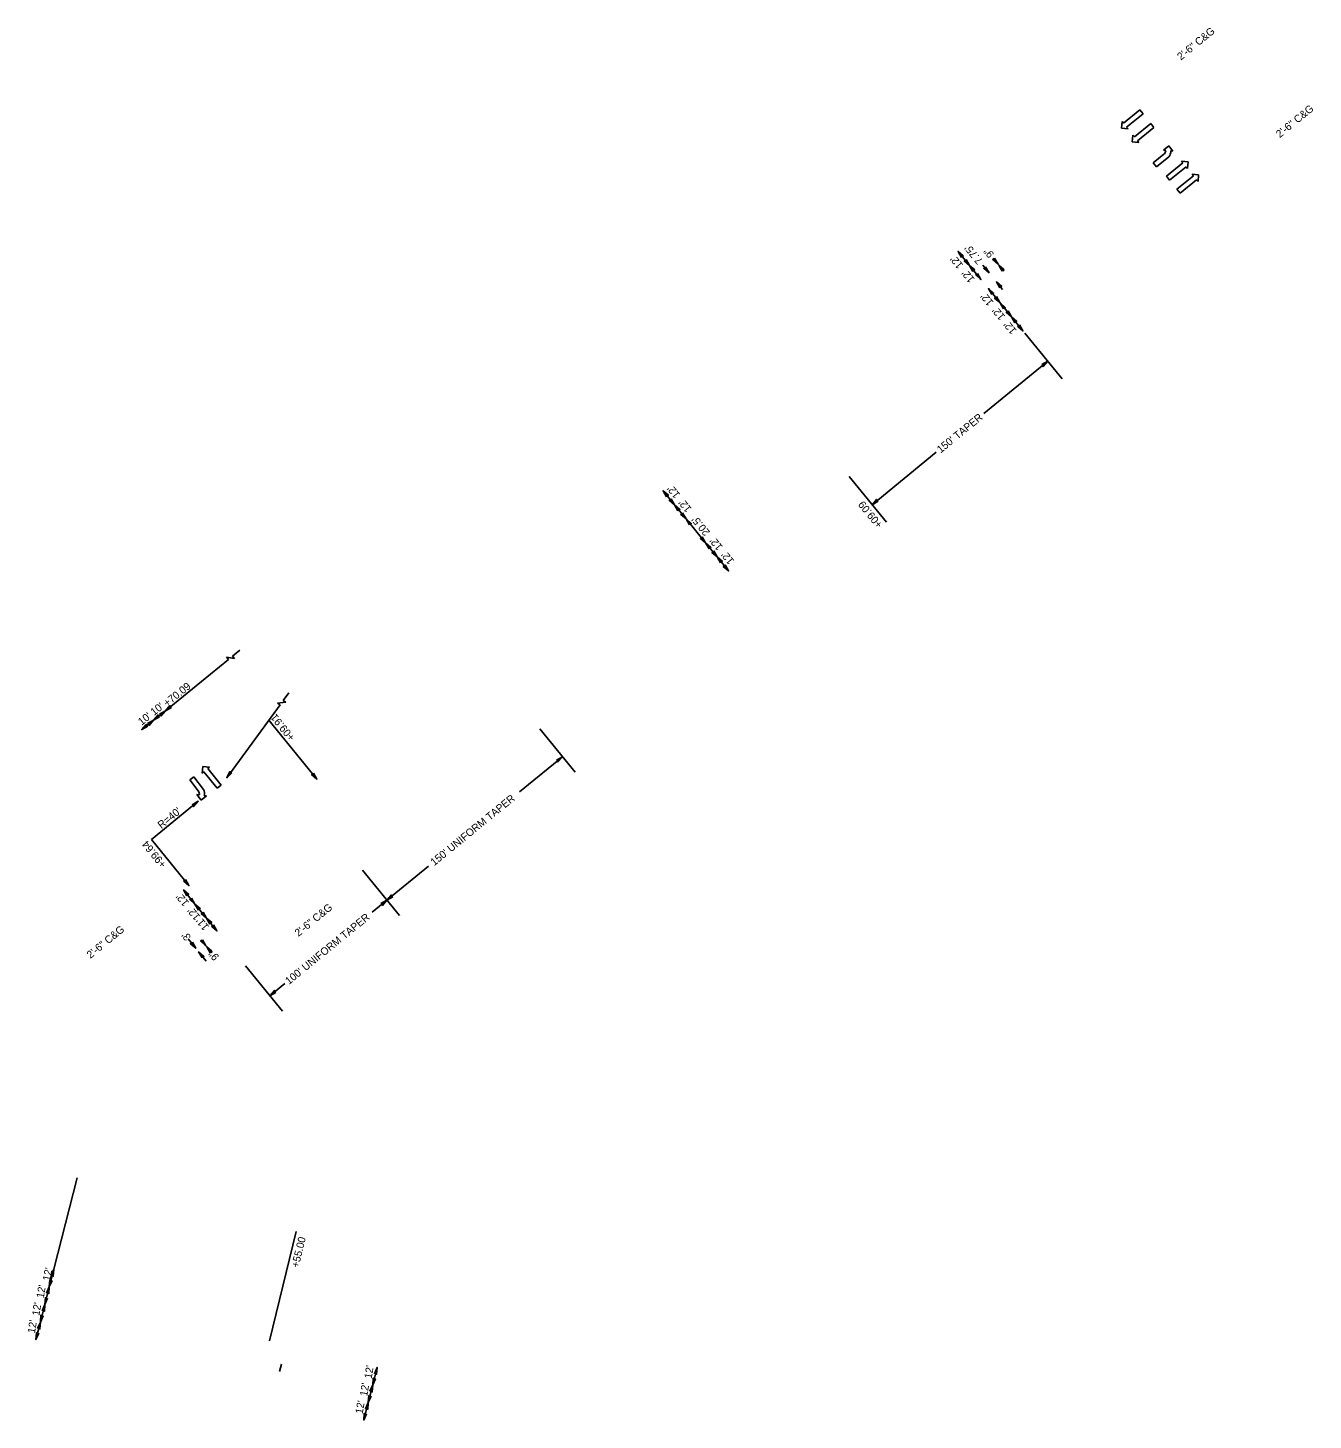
# Model space of a CAD drawing. Extents: x 2320991 to 2332664, y 598057 to 612602.
# Drawn here: x 2322011 to 2322862, y 598057 to 598978 of the extents above; entities that cross this region are included whole.
import ezdxf

# ---------------------------------------------------------------- set-up
doc = ezdxf.new("R2010")
doc.units = 0
for name, color, linetype in [('Prop Dimension', 7, 'Continuous'), ('Prop Dimension Text', 7, 'Continuous'), ('Prop Horizontal Alignment Tick Small', 7, 'Continuous'), ('Prop Lane Arrow CELL', 7, 'Continuous'), ('Prop Terminator CELL', 7, 'Continuous')]:
    doc.layers.add(name, color=color, linetype=linetype)

msp = doc.modelspace()

# ---------------------------------------------------------------- linework, layer by layer
at = {"layer": 'Prop Dimension'}
for p, q in [((2322626.9, 598830.22), (2322634.48, 598820.92)), ((2322634.48, 598820.92), (2322642.07, 598811.62)), ((2322643.28, 598821.1), (2322647.39, 598816.06)), ((2322650.03, 598825.85), (2322653.34, 598821.79)), ((2322653.81, 598821.21), (2322657.12, 598817.15)), ((2322646.98, 598805.62), (2322654.56, 598796.32)), ((2322652.29, 598810.06), (2322656.4, 598805.02)), ((2322654.66, 598796.21), (2322662.25, 598786.92)), ((2322662.25, 598786.92), (2322669.84, 598777.62)), ((2322671.01, 598776.19), (2322695.7, 598745.94)), ((2322643.86, 598722.98), (2322686.22, 598757.56)), ((2322570, 598662.68), (2322612.49, 598697.37)), ((2322554.79, 598681.31), (2322579.48, 598651.06)), ((2322431.75, 598671.87), (2322439.34, 598662.57)), ((2322439.34, 598662.57), (2322446.93, 598653.28)), ((2322446.93, 598653.28), (2322459.89, 598637.4)), ((2322459.89, 598637.4), (2322467.48, 598628.1)), ((2322467.48, 598628.1), (2322475.07, 598618.81)), ((2322146.88, 598562.55), (2322151.73, 598566.51)), ((2322102.46, 598526.28), (2322144.08, 598560.27)), ((2322180.43, 598533.17), (2322184.17, 598538.19)), ((2322086.75, 598513.9), (2322102.46, 598526.28)), ((2322143.07, 598482.05), (2322178.27, 598530.27)), ((2322202.68, 598481.18), (2322170.87, 598520.14)), ((2322350.22, 598514.3), (2322373.49, 598485.79)), ((2322336.65, 598472.66), (2322365.19, 598495.96)), ((2322124.13, 598466.48), (2322093.15, 598441.19)), ((2322118.02, 598410.74), (2322093.15, 598441.19)), ((2322232.84, 598420.89), (2322257.29, 598390.93)), ((2322248.99, 598401.09), (2322276.56, 598423.6)), ((2322122.01, 598398.51), (2322114.42, 598407.8)), ((2322129.6, 598389.21), (2322122.01, 598398.51)), ((2322248.99, 598401.09), (2322239.34, 598393.21)), ((2322136.56, 598380.69), (2322129.6, 598389.21)), ((2322117.44, 598375.41), (2322122.5, 598369.22)), ((2322125.95, 598374.92), (2322129.26, 598370.86)), ((2322129.74, 598370.28), (2322133.05, 598366.22)), ((2322124.4, 598366.89), (2322128.59, 598361.76)), ((2322124.4, 598366.89), (2322129.46, 598360.7)), ((2322155.37, 598357.65), (2322179.83, 598327.69)), ((2322181.49, 598345.99), (2322171.53, 598337.85)), ((2322028.68, 598157), (2322043.95, 598217.49)), ((2322171.25, 598109.47), (2322189, 598181.97)), ((2322028.55, 598156.9), (2322025.61, 598145.27)), ((2322025.61, 598145.27), (2322022.67, 598133.63)), ((2322022.67, 598133.63), (2322019.72, 598122)), ((2322019.72, 598122), (2322016.78, 598110.37)), ((2322242.53, 598092.01), (2322239.59, 598080.37)), ((2322239.59, 598080.37), (2322236.65, 598068.74)), ((2322236.65, 598068.74), (2322233.7, 598057.11))]:
    msp.add_line(p, q, dxfattribs=at)
at = {"layer": 'Prop Dimension Text'}
for p, q in [((2322146.88, 598562.55), (2322148.15, 598561)), ((2322142.82, 598561.82), (2322148.15, 598561)), ((2322144.08, 598560.27), (2322142.82, 598561.82)), ((2322176.67, 598531.47), (2322182.03, 598531.97)), ((2322178.27, 598530.27), (2322176.67, 598531.47)), ((2322180.43, 598533.17), (2322182.03, 598531.97))]:
    msp.add_line(p, q, dxfattribs=at)
at = {"layer": 'Prop Horizontal Alignment Tick Small'}
msp.add_line((2322177.99, 598089.28), (2322179.21, 598094.13), dxfattribs=at)
at = {"layer": 'Prop Lane Arrow CELL'}
for p, q in [((2322736.34, 598914.96), (2322747.21, 598923.78)), ((2322747.21, 598923.78), (2322749.29, 598921.22)), ((2322734.97, 598911.66), (2322735.4, 598916.13)), ((2322735.4, 598916.13), (2322736.34, 598914.96)), ((2322749.29, 598921.22), (2322738.42, 598912.4)), ((2322743.55, 598905.91), (2322754.42, 598914.73)), ((2322754.42, 598914.73), (2322756.5, 598912.17)), ((2322739.37, 598911.23), (2322734.97, 598911.66)), ((2322738.42, 598912.4), (2322739.37, 598911.23)), ((2322742.17, 598902.61), (2322742.6, 598907.08)), ((2322742.6, 598907.08), (2322743.55, 598905.91)), ((2322756.5, 598912.17), (2322745.63, 598903.35)), ((2322745.63, 598903.35), (2322746.57, 598902.19)), ((2322746.57, 598902.19), (2322742.17, 598902.61)), ((2322763.12, 598894.52), (2322756.03, 598888.73)), ((2322766.37, 598899.95), (2322762.85, 598897.14)), ((2322762.85, 598897.14), (2322764.33, 598896.99)), ((2322769.12, 598896.51), (2322766.37, 598899.95)), ((2322767.64, 598896.65), (2322769.12, 598896.51)), ((2322756.03, 598888.73), (2322758.12, 598886.17)), ((2322758.12, 598886.17), (2322766.29, 598892.85)), ((2322764.78, 598879.89), (2322775.65, 598888.72)), ((2322777.73, 598886.15), (2322766.86, 598877.33)), ((2322775.65, 598888.72), (2322774.7, 598889.88)), ((2322774.7, 598889.88), (2322779.1, 598889.46)), ((2322778.67, 598884.99), (2322777.73, 598886.15)), ((2322779.1, 598889.46), (2322778.67, 598884.99)), ((2322766.86, 598877.33), (2322764.78, 598879.89)), ((2322771.77, 598871.32), (2322782.65, 598880.15)), ((2322784.73, 598877.58), (2322773.85, 598868.76)), ((2322782.65, 598880.15), (2322781.7, 598881.31)), ((2322781.7, 598881.31), (2322786.1, 598880.89)), ((2322785.67, 598876.42), (2322784.73, 598877.58)), ((2322786.1, 598880.89), (2322785.67, 598876.42)), ((2322773.85, 598868.76), (2322771.77, 598871.32)), ((2322126.78, 598485.05), (2322127.2, 598489.45)), ((2322127.2, 598489.45), (2322131.67, 598489.02)), ((2322131.67, 598489.02), (2322130.5, 598488.07)), ((2322118.61, 598480.6), (2322121.22, 598482.61)), ((2322124.19, 598473.35), (2322118.61, 598480.6)), ((2322121.22, 598482.61), (2322127.66, 598474.26)), ((2322127.94, 598485.99), (2322126.78, 598485.05)), ((2322136.76, 598475.12), (2322127.94, 598485.99)), ((2322130.5, 598488.07), (2322139.32, 598477.2)), ((2322126.12, 598467.32), (2322123.33, 598470.86)), ((2322123.33, 598470.86), (2322124.8, 598470.67)), ((2322139.32, 598477.2), (2322136.76, 598475.12)), ((2322129.57, 598470.05), (2322126.12, 598467.32)), ((2322128.1, 598470.24), (2322129.57, 598470.05))]:
    msp.add_line(p, q, dxfattribs=at)
for centre, radius, start, end in [((2322761.07, 598897.05), 3.27, 309.22799, 358.88617), ((2322762.41, 598896.35), 5.25, 317.90406, 3.21576), ((2322121.61, 598471.35), 3.27, 347.95273, 37.61091), ((2322123.07, 598471.72), 5.25, 343.62314, 28.93483)]:
    msp.add_arc(centre, radius, start, end, dxfattribs=at)
at = {"layer": 'Prop Terminator CELL'}
for points in [[(2322629.14, 598826.24), (2322626.9, 598830.22), (2322630.38, 598827.22), (2322629.39, 598827.16)], [(2322632.24, 598824.9), (2322634.48, 598820.92), (2322631, 598823.92), (2322631.99, 598823.98)], [(2322636.73, 598816.94), (2322634.48, 598820.92), (2322637.97, 598817.92), (2322636.98, 598817.86)], [(2322651.09, 598825.77), (2322653.34, 598821.79), (2322649.86, 598824.79), (2322650.84, 598824.85)], [(2322656.06, 598817.23), (2322653.81, 598821.21), (2322657.29, 598818.21), (2322656.31, 598818.15)], [(2322639.83, 598815.6), (2322642.07, 598811.62), (2322638.59, 598814.62), (2322639.58, 598814.68)], [(2322645.14, 598820.04), (2322647.39, 598816.06), (2322643.91, 598819.06), (2322644.89, 598819.12)], [(2322649.22, 598801.65), (2322646.97, 598805.62), (2322650.46, 598802.62), (2322649.47, 598802.56)], [(2322654.54, 598806.08), (2322652.29, 598810.06), (2322655.77, 598807.06), (2322654.79, 598807)], [(2322652.32, 598800.3), (2322654.56, 598796.32), (2322651.08, 598799.32), (2322652.07, 598799.38)], [(2322656.9, 598792.24), (2322654.66, 598796.21), (2322658.14, 598793.21), (2322657.16, 598793.15)], [(2322660, 598790.89), (2322662.25, 598786.92), (2322658.77, 598789.92), (2322659.75, 598789.98)], [(2322664.49, 598782.94), (2322662.25, 598786.92), (2322665.73, 598783.92), (2322664.75, 598783.86)], [(2322667.59, 598781.6), (2322669.84, 598777.62), (2322666.36, 598780.62), (2322667.34, 598780.68)], [(2322682.24, 598755.31), (2322686.22, 598757.56), (2322683.22, 598754.07), (2322683.16, 598755.06)], [(2322434, 598667.89), (2322431.75, 598671.87), (2322435.23, 598668.87), (2322434.25, 598668.81)], [(2322437.09, 598666.55), (2322439.34, 598662.57), (2322435.86, 598665.57), (2322436.84, 598665.63)], [(2322573.97, 598664.92), (2322570, 598662.68), (2322573, 598666.16), (2322573.06, 598665.17)], [(2322441.58, 598658.6), (2322439.34, 598662.57), (2322442.82, 598659.57), (2322441.84, 598659.51)], [(2322444.68, 598657.25), (2322446.93, 598653.28), (2322443.45, 598656.28), (2322444.43, 598656.34)], [(2322449.17, 598649.3), (2322446.93, 598653.28), (2322450.41, 598650.28), (2322449.43, 598650.22)], [(2322457.65, 598641.37), (2322459.89, 598637.4), (2322456.41, 598640.4), (2322457.39, 598640.46)], [(2322462.14, 598633.42), (2322459.89, 598637.4), (2322463.37, 598634.4), (2322462.39, 598634.34)], [(2322465.24, 598632.08), (2322467.48, 598628.1), (2322464, 598631.1), (2322464.98, 598631.16)], [(2322469.73, 598624.13), (2322467.48, 598628.1), (2322470.96, 598625.1), (2322469.98, 598625.04)], [(2322472.82, 598622.78), (2322475.07, 598618.81), (2322471.59, 598621.81), (2322472.57, 598621.87)], [(2322098.48, 598524.04), (2322102.46, 598526.28), (2322099.46, 598522.8), (2322099.4, 598523.79)], [(2322106.44, 598528.53), (2322102.46, 598526.28), (2322105.46, 598529.77), (2322105.52, 598528.78)], [(2322090.73, 598516.15), (2322086.75, 598513.9), (2322089.75, 598517.38), (2322089.81, 598516.4)], [(2322090.63, 598517.85), (2322094.61, 598520.09), (2322091.61, 598516.61), (2322091.55, 598517.6)], [(2322098.58, 598522.34), (2322094.61, 598520.09), (2322097.61, 598523.58), (2322097.67, 598522.59)], [(2322361.21, 598493.71), (2322365.19, 598495.96), (2322362.19, 598492.47), (2322362.13, 598493.46)], [(2322146.35, 598485.23), (2322143.07, 598482.05), (2322145.09, 598486.18), (2322145.4, 598485.24)], [(2322200.43, 598485.16), (2322202.68, 598481.18), (2322199.2, 598484.18), (2322200.18, 598484.24)], [(2322120.16, 598464.24), (2322124.13, 598466.48), (2322121.13, 598463), (2322121.07, 598463.99)], [(2322116.67, 598403.83), (2322114.42, 598407.8), (2322117.91, 598404.8), (2322116.92, 598404.74)], [(2322115.77, 598414.71), (2322118.02, 598410.74), (2322114.54, 598413.74), (2322115.52, 598413.8)], [(2322119.77, 598402.48), (2322122.01, 598398.51), (2322118.53, 598401.51), (2322119.52, 598401.57)], [(2322124.26, 598394.53), (2322122.01, 598398.51), (2322125.49, 598395.51), (2322124.51, 598395.45)], [(2322245.02, 598398.85), (2322248.99, 598401.09), (2322245.99, 598397.61), (2322245.93, 598398.6)], [(2322252.97, 598403.34), (2322248.99, 598401.09), (2322251.99, 598404.58), (2322252.05, 598403.59)], [(2322127.36, 598393.19), (2322129.6, 598389.21), (2322126.12, 598392.21), (2322127.1, 598392.27)], [(2322131.85, 598385.24), (2322129.6, 598389.21), (2322133.08, 598386.21), (2322132.1, 598386.15)], [(2322134.31, 598384.67), (2322136.56, 598380.69), (2322133.08, 598383.69), (2322134.06, 598383.75)], [(2322120.26, 598373.19), (2322122.5, 598369.22), (2322119.02, 598372.22), (2322120, 598372.28)], [(2322127.02, 598374.84), (2322129.26, 598370.86), (2322125.78, 598373.86), (2322126.76, 598373.92)], [(2322131.98, 598366.3), (2322129.74, 598370.28), (2322133.22, 598367.28), (2322132.23, 598367.22)], [(2322126.65, 598362.92), (2322124.4, 598366.89), (2322127.88, 598363.89), (2322126.9, 598363.83)], [(2322175.51, 598340.1), (2322171.53, 598337.85), (2322174.53, 598341.34), (2322174.59, 598340.35)], [(2322027.47, 598149.44), (2322025.61, 598145.27), (2322025.94, 598149.85), (2322026.58, 598149.1)], [(2322026.7, 598152.73), (2322028.55, 598156.9), (2322028.22, 598152.32), (2322027.59, 598153.07)], [(2322023.75, 598141.09), (2322025.61, 598145.27), (2322025.28, 598140.68), (2322024.64, 598141.44)], [(2322020.81, 598129.46), (2322022.67, 598133.63), (2322022.33, 598129.05), (2322021.7, 598129.8)], [(2322024.52, 598137.81), (2322022.67, 598133.63), (2322023, 598138.22), (2322023.64, 598137.46)], [(2322017.87, 598117.83), (2322019.72, 598122), (2322019.39, 598117.42), (2322018.75, 598118.17)], [(2322021.58, 598126.17), (2322019.72, 598122), (2322020.06, 598126.58), (2322020.69, 598125.83)], [(2322018.63, 598114.54), (2322016.78, 598110.37), (2322017.11, 598114.95), (2322017.75, 598114.2)], [(2322241.45, 598084.54), (2322239.59, 598080.37), (2322239.92, 598084.95), (2322240.56, 598084.2)], [(2322240.68, 598087.83), (2322242.53, 598092.01), (2322242.2, 598087.42), (2322241.57, 598088.18)], [(2322237.73, 598076.2), (2322239.59, 598080.37), (2322239.26, 598075.79), (2322238.62, 598076.54)], [(2322234.79, 598064.57), (2322236.65, 598068.74), (2322236.31, 598064.16), (2322235.68, 598064.91)], [(2322238.5, 598072.91), (2322236.65, 598068.74), (2322236.98, 598073.32), (2322237.61, 598072.57)], [(2322235.56, 598061.28), (2322233.7, 598057.11), (2322234.04, 598061.69), (2322234.67, 598060.93)]]:
    msp.add_lwpolyline(points, close=True, dxfattribs=at)

# ---------------------------------------------------------------- texts
at = {"layer": 'Prop Dimension'}
msp.add_text('+55.00', height=5, rotation=76.23807, dxfattribs=at).set_placement((2322190.51, 598157.61))
at = {"layer": 'Prop Dimension Text'}
for s, rotation, p in [('2\'-6" C&G', 39.22799, (2322774.33, 598956.39)), ('2\'-6" C&G', 39.22799, (2322839.77, 598905.08)), ("7.75'", 129.22799, (2322643.64, 598824.19)), ('9"', 129.22799, (2322651.1, 598828.43)), ("12'", 129.22799, (2322630.61, 598821.22)), ("12'", 129.22799, (2322638.2, 598811.93)), ("12'", 129.22799, (2322650.69, 598796.63)), ("12'", 129.22799, (2322658.37, 598787.22)), ("12'", 129.22799, (2322665.96, 598777.92)), ("150' TAPER", 39.22799, (2322615.4, 598696.52)), ("12'", 129.22799, (2322443.35, 598669.38)), ("12'", 129.22799, (2322450.94, 598660.09)), ('+09.09', 129.22799, (2322577.31, 598649.68)), ("20.5'", 129.22799, (2322463.07, 598644.57)), ("12'", 129.22799, (2322471.5, 598634.91)), ("12'", 129.22799, (2322479.09, 598625.61)), ('+70.09', 38.71959, (2322103.6, 598528.8)), ("10'", 38.24817, (2322094.94, 598522.88)), ("10'", 38.24817, (2322086.72, 598516.4)), ('+09.91', 129.22799, (2322188.48, 598508.88)), ("150' UNIFORM TAPER", 39.22799, (2322280.31, 598423.52)), ("R=40'", 39.22799, (2322099.78, 598448.05)), ('+99.64', 129.22799, (2322103.39, 598424.97)), ("12'", 129.22799, (2322118.34, 598399.5)), ('2\'-6" C&G', 39.22799, (2322190.45, 598376.7)), ("12'", 129.22799, (2322125.93, 598390.21)), ("11'", 129.22799, (2322131.58, 598383.49)), ("100' UNIFORM TAPER", 39.22799, (2322184.17, 598344.94)), ('2\'-6" C&G', 39.22799, (2322052.84, 598362.18)), ("3'", 129.22799, (2322119.69, 598376.8)), ('9"', 129.22799, (2322138.31, 598363.67)), ("12'", 78.96084, (2322026.05, 598148.92)), ("12'", 80.66924, (2322021.95, 598137.54)), ("12'", 80.66924, (2322019, 598125.91)), ("12'", 80.66924, (2322016.06, 598114.28)), ("12'", 80.66924, (2322238.87, 598084.28)), ("12'", 80.66924, (2322235.93, 598072.65)), ("12'", 80.66924, (2322232.98, 598061.02))]:
    msp.add_text(s, height=5, rotation=rotation, dxfattribs=at).set_placement(p)

doc.saveas('drawing.dxf')
